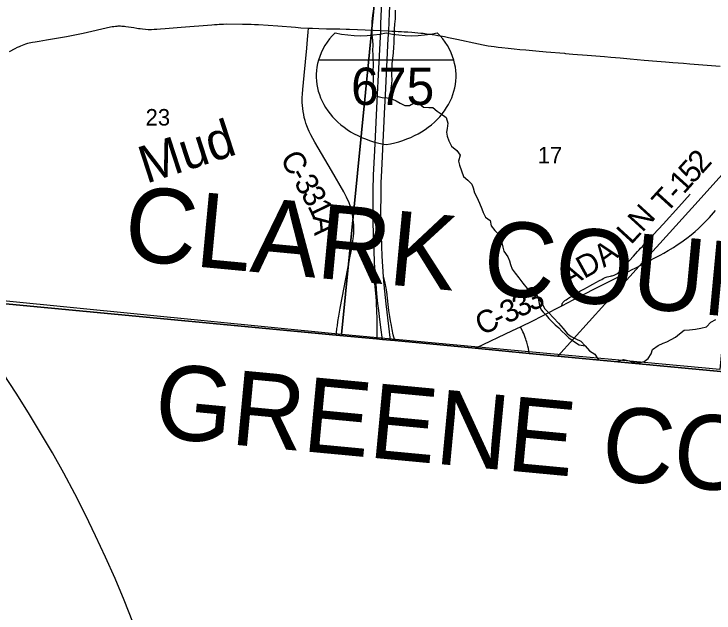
# Model space of a CAD drawing. Extents: x 0 to 680, y 0 to 440.
# Drawn here: x 174.06 to 201.89, y 223.53 to 247.33 of the extents above; entities that cross this region are included whole.
import ezdxf

# ---------------------------------------------------------------- set-up
doc = ezdxf.new("R2010")
doc.units = 0
for name, color, linetype in [('GM_X_Adjacent_County', 7, 'Continuous'), ('GM_X_Adjacent_County_Text', 7, 'Continuous'), ('GM_X_County', 7, 'Continuous'), ('GM_X_County_Road', 7, 'Continuous'), ('GM_X_County_Road_Text', 7, 'Continuous'), ('GM_X_Interchange_Ramps', 7, 'Continuous'), ('GM_X_Interstate_Location', 7, 'Continuous'), ('GM_X_Interstate_Route', 7, 'Continuous'), ('GM_X_Interstate_Shield', 7, 'Continuous'), ('GM_X_Minor_Lake', 7, 'Continuous'), ('GM_X_Minor_River', 7, 'Continuous'), ('GM_X_Minor_River_Text', 7, 'Continuous'), ('GM_X_Rail_Line', 7, 'Continuous'), ('GM_X_Section', 7, 'Continuous'), ('GM_X_Section_Text', 7, 'Continuous'), ('GM_X_State_Route', 7, 'Continuous'), ('GM_X_Township', 7, 'Continuous'), ('GM_X_Township_Road', 7, 'Continuous'), ('GM_X_Township_Road_Text', 7, 'Continuous'), ('SH_Text', 7, 'Continuous')]:
    doc.layers.add(name, color=color, linetype=linetype)

msp = doc.modelspace()

# ---------------------------------------------------------------- linework, layer by layer
at = {"layer": 'GM_X_Adjacent_County'}
for points in [[(147.293, 330.96), (144.577, 302.142), (144.51, 301.336), (143.553, 290.485), (143.529, 290.136), (141.787, 270.726), (141.629, 267.688), (140.594, 256.41), (140.493, 255.146), (140.47, 254.902), (140.455, 254.776), (140.389, 254.084), (139.425, 244.118), (138.983, 239.223), (153.32, 237.849), (163.933, 236.734), (186.866, 234.57), (188.472, 234.42), (188.705, 234.396), (189.027, 234.365), (189.199, 234.349), (192.391, 234.048), (194.54, 233.845), (222.573, 231.206)], [(222.573, 231.206), (194.54, 233.845), (192.391, 234.048), (189.199, 234.349), (189.027, 234.365), (188.705, 234.396), (188.472, 234.42), (186.866, 234.57), (163.933, 236.734), (153.32, 237.849), (138.983, 239.223), (138.264, 231.413), (137.541, 223.533), (133.372, 223.921), (132.763, 223.977), (126.921, 224.521)], [(222.573, 231.206), (194.54, 233.845), (192.391, 234.048), (189.199, 234.349), (189.027, 234.365), (188.705, 234.396), (188.472, 234.42), (186.866, 234.57), (163.933, 236.734), (153.32, 237.849), (138.983, 239.223), (138.264, 231.413), (137.541, 223.533), (133.372, 223.921), (132.763, 223.977), (126.921, 224.521)]]:
    msp.add_lwpolyline(points, dxfattribs=at)
at = {"layer": 'GM_X_County'}
msp.add_lwpolyline([(147.293, 330.96), (144.577, 302.142), (144.51, 301.336), (143.553, 290.485), (143.529, 290.136), (141.787, 270.726), (141.629, 267.688), (140.594, 256.41), (140.493, 255.146), (140.47, 254.902), (140.455, 254.776), (140.389, 254.084), (139.425, 244.118), (138.983, 239.223), (153.32, 237.849), (163.933, 236.734), (186.866, 234.57), (188.472, 234.42), (188.705, 234.396), (189.027, 234.365), (189.199, 234.349), (192.391, 234.048), (194.54, 233.845), (222.573, 231.206)], dxfattribs=at)
at = {"layer": 'GM_X_County_Road'}
for points in [[(173.88, 245.834), (174.115, 245.96), (174.208, 246.007), (174.276, 246.04), (174.34, 246.069), (174.399, 246.091), (174.472, 246.117), (174.537, 246.141), (174.607, 246.164), (174.664, 246.179), (174.729, 246.194), (174.798, 246.209), (174.9, 246.227), (175.066, 246.254), (175.358, 246.302), (176.147, 246.435), (176.478, 246.499), (176.814, 246.568), (177.905, 246.817), (177.965, 246.827), (178.029, 246.838), (178.098, 246.846), (178.13, 246.849), (178.163, 246.852), (178.205, 246.854), (178.255, 246.854), (178.299, 246.853), (178.345, 246.851), (178.395, 246.847), (178.452, 246.841), (178.511, 246.835), (178.614, 246.821), (178.827, 246.789), (178.948, 246.77), (179.014, 246.759), (179.084, 246.748), (179.176, 246.736), (179.284, 246.725), (179.392, 246.719), (179.463, 246.717), (179.534, 246.719), (179.634, 246.721), (179.743, 246.727), (179.884, 246.737), (180.078, 246.751), (180.712, 246.806), (181.93, 246.904), (182.038, 246.911), (182.136, 246.918), (182.213, 246.924), (182.297, 246.928), (182.396, 246.931), (182.507, 246.933), (183.139, 246.932), (183.224, 246.93), (183.379, 246.929), (183.491, 246.924), (183.626, 246.918), (183.777, 246.91), (184.548, 246.853), (185.254, 246.8), (185.462, 246.785), (185.763, 246.767), (185.768, 246.767)], [(187.372, 237.418), (187.414, 237.638), (187.462, 237.887), (187.515, 238.195), (187.531, 238.301), (187.547, 238.405), (187.554, 238.488), (187.566, 238.621), (187.571, 238.744), (187.571, 238.857), (187.567, 238.952), (187.561, 239.042), (187.546, 239.177), (187.533, 239.272), (187.517, 239.368), (187.492, 239.479), (187.459, 239.602), (187.38, 239.83), (187.286, 240.053), (187.176, 240.268), (186.689, 241.107), (186.018, 242.234), (185.856, 242.533), (185.799, 242.656), (185.755, 242.755), (185.705, 242.88), (185.666, 242.99), (185.633, 243.099), (185.601, 243.218), (185.577, 243.339), (185.554, 243.457), (185.54, 243.572), (185.528, 243.687), (185.52, 243.813), (185.519, 243.992), (185.528, 244.163), (185.54, 244.332), (185.566, 244.614), (185.594, 244.883), (185.7, 245.975), (185.735, 246.32), (185.756, 246.61), (185.768, 246.767)], [(185.768, 246.767), (185.93, 246.76), (186.18, 246.752), (186.488, 246.746), (186.817, 246.739), (187.02, 246.734), (187.265, 246.727), (187.399, 246.724), (187.723, 246.712), (188.638, 246.67), (188.956, 246.655), (189.086, 246.647), (189.224, 246.643), (189.337, 246.64), (189.46, 246.632), (189.573, 246.626), (189.72, 246.617), (189.875, 246.605), (189.994, 246.597), (190.116, 246.585), (190.231, 246.573), (190.329, 246.562), (190.464, 246.545), (190.613, 246.524), (190.688, 246.515), (190.788, 246.5), (190.906, 246.481), (191.016, 246.462), (191.17, 246.433), (191.336, 246.401), (191.666, 246.329), (192.521, 246.145), (192.716, 246.107), (192.908, 246.071), (193.143, 246.036), (193.313, 246.011), (193.46, 245.993), (193.7, 245.966), (193.938, 245.943), (194.175, 245.922), (194.41, 245.901), (194.806, 245.865), (195.22, 245.829), (195.945, 245.768)], [(195.945, 245.768), (195.986, 245.764), (196.282, 245.739), (196.852, 245.693), (197.534, 245.638), (197.789, 245.619), (198.163, 245.587), (198.559, 245.552), (199.112, 245.5), (199.612, 245.453), (199.965, 245.427), (200.248, 245.406), (200.676, 245.373), (200.927, 245.354), (202.138, 245.26)], [(195.837, 235.733), (196.095, 235.867), (196.485, 236.072), (196.748, 236.21), (197.144, 236.408), (197.427, 236.556), (197.98, 236.839), (198.513, 237.112), (198.606, 237.164), (198.78, 237.249), (199.01, 237.364), (199.223, 237.474), (199.515, 237.627), (199.749, 237.75), (199.892, 237.828), (200.07, 237.932), (200.272, 238.054), (200.427, 238.151), (200.573, 238.25), (200.806, 238.418), (200.982, 238.559), (201.135, 238.686), (201.274, 238.81), (201.424, 238.948), (201.542, 239.068), (201.708, 239.24), (201.953, 239.519)], [(186.866, 234.57), (186.877, 234.658), (186.899, 234.826), (186.916, 234.941), (186.941, 235.108), (186.973, 235.321), (187.028, 235.639), (187.333, 237.212), (187.372, 237.418)], [(194.192, 234.898), (194.713, 235.154), (195.621, 235.622), (195.837, 235.733)], [(192.391, 234.048), (192.431, 234.065), (193.884, 234.747), (194.192, 234.898)]]:
    msp.add_lwpolyline(points, dxfattribs=at)
at = {"layer": 'GM_X_Interchange_Ramps'}
msp.add_lwpolyline([(188.409, 237.196), (188.384, 236.994), (188.381, 236.951), (188.379, 236.906), (188.382, 236.861), (188.384, 236.81), (188.397, 236.615), (188.43, 236.232), (188.442, 236.089), (188.453, 235.924), (188.463, 235.739), (188.472, 235.597), (188.477, 235.429), (188.481, 235.318), (188.486, 235.006), (188.488, 234.817), (188.488, 234.755), (188.487, 234.677), (188.481, 234.559), (188.472, 234.42)], dxfattribs=at)
at = {"layer": 'GM_X_Interstate_Route'}
for points in [[(188.705, 234.396), (188.64, 234.869), (188.587, 235.311), (188.56, 235.547), (188.53, 235.83), (188.489, 236.222), (188.47, 236.41), (188.455, 236.614), (188.43, 236.907), (188.409, 237.196), (188.36, 238.206), (188.335, 239.033), (188.333, 239.899), (188.339, 240.335), (188.356, 240.929), (188.4, 241.902), (188.512, 244.149), (188.549, 244.913), (188.638, 246.67), (188.65, 246.948), (188.714, 248.406)], [(188.754, 236.885), (188.7, 237.709), (188.683, 238.103), (188.669, 238.528), (188.658, 238.795), (188.65, 239.031), (188.65, 239.267), (188.649, 239.589), (188.654, 239.993), (188.657, 240.217), (188.66, 240.449), (188.662, 240.621), (188.682, 241.112), (188.803, 243.643), (188.826, 244.106), (188.939, 246.358), (188.956, 246.655), (188.972, 247.001), (188.99, 247.374), (189.04, 248.401)], [(189.027, 234.365), (188.856, 235.81), (188.78, 236.57), (188.754, 236.885)]]:
    msp.add_lwpolyline(points, dxfattribs=at)
at = {"layer": 'GM_X_Interstate_Shield'}
msp.add_line((191.543, 245.499), (186.168, 245.499), dxfattribs=at)
msp.add_line((191.543, 245.499), (186.168, 245.499), dxfattribs=at)
for centre, start_param, end_param in [((189.55, 244.863), 2.47259, 2.911027), ((187.84, 249.245), 4.415841, 5.008937), ((189.871, 249.245), 4.415841, 5.008937), ((188.161, 244.863), 0.230566, 0.669003), ((189.55, 244.863), 2.911027, 4.511031), ((188.161, 244.863), 4.913747, 6.513751)]:
    msp.add_ellipse(centre, major_axis=(3.474, 0), ratio=0.8, start_param=start_param, end_param=end_param, dxfattribs=at)
at = {"layer": 'GM_X_Minor_Lake'}
for points in [[(194.895, 236.042), (194.951, 235.745), (195.02, 235.578), (195.095, 235.482), (195.212, 235.356), (195.323, 235.225), (195.58, 234.972), (195.715, 234.864), (195.843, 234.726), (195.984, 234.594), (196.112, 234.468), (196.253, 234.365), (196.382, 234.28), (196.523, 234.19), (196.765, 234.139)], [(194.895, 236.042), (195.041, 235.833), (195.168, 235.618), (195.314, 235.462), (195.513, 235.258), (195.711, 235.048), (195.886, 234.838), (196.055, 234.64), (196.208, 234.52), (196.402, 234.417), (196.596, 234.325), (196.765, 234.139)]]:
    msp.add_lwpolyline(points, dxfattribs=at)
at = {"layer": 'GM_X_Minor_River'}
for points in [[(188.323, 244.11), (188.33, 244.349), (188.344, 244.521), (188.352, 244.675), (188.354, 244.841), (188.344, 245.013), (188.348, 245.345), (188.339, 245.564), (188.335, 245.719), (188.331, 245.885), (188.34, 246.092), (188.325, 246.294), (188.303, 246.49), (188.3, 246.674), (188.302, 246.84), (188.298, 247.036), (188.325, 247.267), (188.356, 247.444)], [(189.037, 243.958), (189.038, 244.18), (189.052, 244.381), (189.084, 244.559), (189.092, 244.713), (189.088, 244.897), (189.098, 245.17), (189.1, 245.359), (189.12, 245.567), (189.152, 245.78), (189.161, 246.005), (189.169, 246.171), (189.177, 246.325), (189.185, 246.539), (189.182, 246.723), (189.202, 246.924), (189.222, 247.131), (189.231, 247.327), (189.233, 247.481)], [(188.38, 244.087), (188.693, 244.018), (188.894, 243.992), (189.106, 243.942), (189.259, 243.875), (189.412, 243.79), (189.6, 243.693), (189.783, 243.69), (189.938, 243.784), (190.116, 243.811), (190.339, 243.63), (190.557, 243.616), (190.711, 243.608), (190.881, 243.464), (191.04, 243.367), (191.245, 243.216), (191.307, 242.99), (191.275, 242.783), (191.249, 242.629), (191.277, 242.48), (191.346, 242.29), (191.455, 242.075), (191.66, 241.912), (191.8, 241.715), (191.738, 241.478), (191.771, 241.318), (191.846, 241.103), (191.926, 240.877), (192.101, 240.726), (192.265, 240.57), (192.311, 240.421), (192.373, 240.219), (192.454, 240.046), (192.563, 239.807), (192.655, 239.593), (192.713, 239.444), (192.805, 239.253), (192.987, 239.126), (193.032, 238.912), (193.177, 238.72), (193.358, 238.546), (193.516, 238.42), (193.449, 238.231), (193.488, 238.07), (193.54, 237.909), (193.691, 237.682), (193.76, 237.521), (193.799, 237.372), (193.868, 237.188), (193.979, 237.032), (194.136, 236.84), (194.287, 236.637), (194.462, 236.421), (194.65, 236.3), (194.832, 236.191), (194.895, 236.042), (195.041, 235.833), (195.168, 235.618), (195.314, 235.462), (195.513, 235.258), (195.711, 235.048), (195.886, 234.838), (196.055, 234.64), (196.208, 234.52), (196.402, 234.417), (196.596, 234.325), (196.765, 234.139), (196.94, 233.947), (197.157, 233.814), (197.244, 233.665), (197.291, 233.59)], [(198.054, 233.518), (198.101, 233.554), (198.308, 233.599), (198.515, 233.554), (198.733, 233.487), (198.916, 233.472), (199.112, 233.523), (199.267, 233.64), (199.394, 233.828), (199.443, 234), (199.664, 234.157), (199.861, 234.256), (200.015, 234.301), (200.188, 234.4), (200.355, 234.487), (200.516, 234.627), (200.707, 234.761), (200.914, 234.777), (201.151, 234.803), (201.359, 234.848), (201.596, 234.899), (201.758, 235.087), (201.961, 235.191)]]:
    msp.add_lwpolyline(points, dxfattribs=at)
at = {"layer": 'GM_X_Rail_Line'}
msp.add_lwpolyline([(195.679, 233.738), (198.792, 237.171), (199.035, 237.44), (199.731, 238.212), (201.258, 239.898), (201.957, 240.671), (202.495, 241.261), (203.557, 242.441), (204.762, 243.764), (205.68, 244.779), (207.438, 246.728), (208.95, 248.397), (210.463, 250.073), (211.618, 251.353), (211.745, 251.485), (215.274, 255.394), (220.659, 261.341)], dxfattribs=at)
at = {"layer": 'GM_X_Section'}
for points in [[(172.459, 252.156), (188.668, 250.631), (187.086, 234.593), (170.955, 236.201)], [(188.668, 250.631), (203.666, 249.238), (202.126, 233.205), (187.086, 234.593)]]:
    msp.add_lwpolyline(points, close=True, dxfattribs=at)
at = {"layer": 'GM_X_State_Route'}
msp.add_lwpolyline([(189.199, 234.349), (189.139, 234.58), (189.093, 234.788), (189.062, 234.95), (189.03, 235.132), (189.001, 235.312), (188.967, 235.551), (188.936, 235.792), (188.919, 235.923), (188.877, 236.29), (188.856, 236.453), (188.849, 236.5), (188.836, 236.575), (188.821, 236.64), (188.754, 236.885)], dxfattribs=at)
at = {"layer": 'GM_X_Township'}
msp.add_lwpolyline([(163.933, 236.734), (186.866, 234.57), (188.472, 234.42), (188.705, 234.396), (189.027, 234.365), (189.199, 234.349), (192.391, 234.048), (194.54, 233.845), (222.573, 231.206)], dxfattribs=at)
at = {"layer": 'GM_X_Township_Road'}
for points in [[(200.489, 239.672), (200.938, 240.171)], [(198.399, 237.392), (198.535, 237.541), (198.685, 237.707), (198.767, 237.799), (198.849, 237.89), (198.915, 237.962), (198.969, 238.018), (199.042, 238.092), (199.101, 238.155), (199.14, 238.197), (199.287, 238.355), (199.862, 238.974), (200.489, 239.672)], [(195.837, 235.733), (195.842, 235.763), (195.848, 235.792), (195.857, 235.821), (195.867, 235.844), (195.878, 235.864), (195.891, 235.879), (195.904, 235.894), (195.926, 235.914), (195.956, 235.94), (196.005, 235.975), (196.058, 236.007), (196.144, 236.06), (196.223, 236.109), (196.364, 236.2), (196.47, 236.263), (196.56, 236.314), (196.71, 236.398), (196.858, 236.475), (196.95, 236.528), (197.073, 236.596), (197.22, 236.676), (197.304, 236.722), (197.367, 236.757), (197.424, 236.785), (197.477, 236.813), (197.51, 236.831), (197.558, 236.853), (197.596, 236.868), (197.647, 236.885), (197.714, 236.901), (197.768, 236.913), (197.81, 236.923), (197.843, 236.93), (197.885, 236.941), (197.922, 236.953), (197.951, 236.965), (197.979, 236.98), (198.028, 237.009), (198.061, 237.033), (198.087, 237.056), (198.135, 237.104), (198.201, 237.172), (198.308, 237.29), (198.393, 237.384), (198.399, 237.392)], [(194.54, 233.845), (194.526, 233.945), (194.509, 234.042), (194.492, 234.13), (194.479, 234.184), (194.467, 234.23), (194.447, 234.293), (194.426, 234.356), (194.408, 234.406), (194.385, 234.473), (194.355, 234.55), (194.323, 234.628), (194.289, 234.701), (194.192, 234.898)]]:
    msp.add_lwpolyline(points, dxfattribs=at)
at = {"layer": 'SH_Text'}
msp.add_arc((131.078, 204.562), 51.209, 12.8217, 79.4318, dxfattribs=at)

# ---------------------------------------------------------------- texts
at = {"layer": 'GM_X_Adjacent_County_Text'}
for s, rotation, p in [('CLARK COUNTY', 354.6286, (178.361, 237.572)), ('GREENE COUNTY', 354.6158, (179.563, 230.521))]:
    msp.add_text(s, height=2.96462, rotation=rotation, dxfattribs=at).set_placement(p)
at = {"layer": 'GM_X_County_Road_Text'}
for s, rotation, p in [('C', 300.275, (184.619, 241.584)), ('3', 300.2587, (185.171, 240.638)), ('-', 300.2716, (184.987, 240.953)), ('3', 300.1793, (185.447, 240.165)), ('1', 295.9623, (185.714, 239.706)), ('A', 275.5676, (185.932, 239.294)), ('3', 26.3521, (194.147, 235.248)), ('3', 27.1993, (194.647, 235.496)), ('3', 25.8184, (193.65, 235.007)), ('C', 25.1884, (192.657, 234.54)), ('-', 25.2977, (193.315, 234.849))]:
    msp.add_text(s, height=0.889, rotation=rotation, dxfattribs=at).set_placement(p)
at = {"layer": 'GM_X_Interstate_Location'}
for s in ['-', '.', ',']:
    msp.add_text(s, height=0.00296, dxfattribs=at).set_placement((188.855, 244.455))
msp.add_text('675', height=0.00296, rotation=0, dxfattribs=at).set_placement((187.949, 243.841))
at = {"layer": 'GM_X_Interstate_Shield'}
msp.add_text('675', height=1.4823, dxfattribs=at).set_placement((187.461, 243.715))
at = {"layer": 'GM_X_Minor_River_Text'}
msp.add_text('Mud', height=1.4822, rotation=18.002, dxfattribs=at).set_placement((179.316, 240.579))
at = {"layer": 'GM_X_Section_Text'}
for s, p in [('23', (179.294, 242.898)), ('17', (194.882, 241.393))]:
    msp.add_text(s, height=0.6552, rotation=0, dxfattribs=at).set_placement(p)
at = {"layer": 'GM_X_Township_Road_Text'}
for s, height, rotation, p in [('2', 0.889, 47.9772, (201.412, 240.95)), ('5', 0.889, 47.9772, (201.048, 240.546)), ('1', 0.889, 47.9772, (200.684, 240.142)), ('T', 0.889, 47.6962, (199.992, 239.379)), ('-', 0.889, 47.9785, (200.442, 239.873)), ('LN', 0.8894, 47.5276, (198.59, 238.134)), ('A', 0.889, 36.1084, (197.511, 237.236)), ('D', 0.889, 28.9083, (196.723, 236.792)), ('A', 0.889, 29.6064, (196.045, 236.407))]:
    msp.add_text(s, height=height, rotation=rotation, dxfattribs=at).set_placement(p)

doc.saveas('drawing.dxf')
